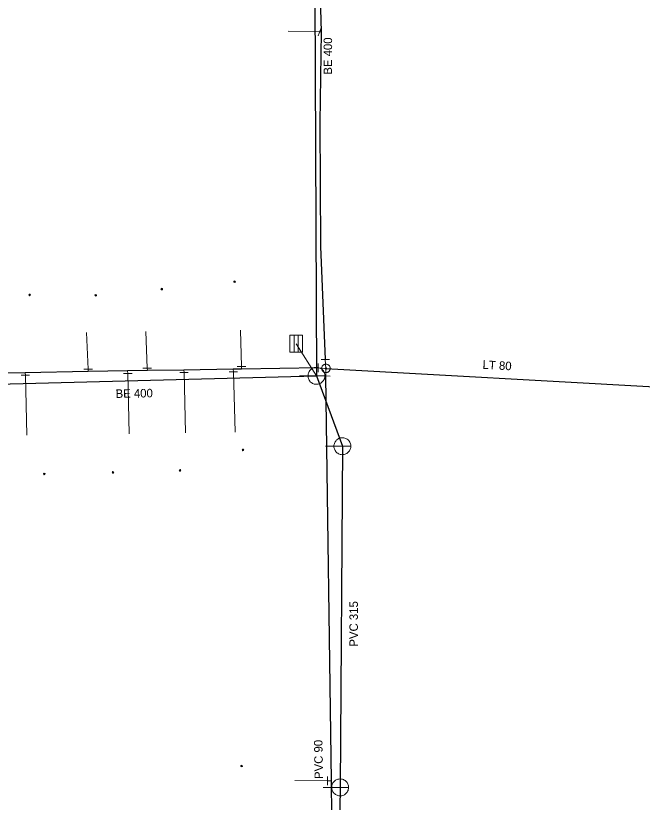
# Model space of a CAD drawing. Extents: x -783064 to -782702, y -1007904 to -1007145.
# Drawn here: x -782974.9 to -782901, y -1007605.1 to -1007512.4 of the extents above; entities that cross this region are included whole.
import ezdxf

# ---------------------------------------------------------------- set-up
doc = ezdxf.new("R2010")
doc.units = 0
doc.header["$LTSCALE"] = 0.4
doc.header["$PDMODE"] = 32
doc.header["$PDSIZE"] = 0.2
for name, color, linetype, lineweight in [('1', 7, 'Continuous', 13), ('11', 7, 'Continuous', 13), ('13', 7, 'Continuous', 13), ('14', 7, 'Continuous', 13), ('17', 7, 'Continuous', 25), ('22', 7, 'Continuous', 13), ('34', 7, 'Continuous', 13), ('47', 7, 'Continuous', 13)]:
    doc.layers.add(name, color=color, linetype=linetype, lineweight=lineweight)

msp = doc.modelspace()

# ---------------------------------------------------------------- linework, layer by layer
at = {"layer": '1'}
for p in [(-782949.079, -1007543.779), (-782973.239, -1007545.329), (-782965.44, -1007545.379), (-782957.66, -1007544.649), (-782948.094, -1007563.596), (-782971.51, -1007566.429), (-782963.42, -1007566.249), (-782955.51, -1007566.019), (-782948.26, -1007600.839)]:
    msp.add_point(p, dxfattribs=at)
at = {"layer": '11'}
msp.add_line((-782941.826, -1007551.093), (-782939.43, -1007554.87), dxfattribs=at)
at = {"layer": '13'}
for p, q in [((-782939.046, -1007514.346), (-782942.776, -1007514.276)), ((-782966.34, -1007554.077), (-782966.541, -1007549.761)), ((-782959.379, -1007553.96), (-782959.526, -1007549.655)), ((-782948.262, -1007553.772), (-782948.368, -1007549.481)), ((-782961.668, -1007554.598), (-782961.517, -1007561.686)), ((-782955.041, -1007554.486), (-782954.849, -1007561.594)), ((-782949.223, -1007554.388), (-782949.024, -1007561.522)), ((-782973.745, -1007554.801), (-782973.568, -1007561.852)), ((-782938.129, -1007602.576), (-782941.986, -1007602.551))]:
    msp.add_line(p, q, dxfattribs=at)
at = {"layer": '14', "lineweight": 25}
for p, q in [((-782939.739, -1007477.92), (-782939.43, -1007554.87)), ((-782980.87, -1007555.95), (-782939.43, -1007554.87)), ((-782939.43, -1007554.87), (-782936.37, -1007563.16)), ((-782936.37, -1007563.16), (-782936.64, -1007603.36))]:
    msp.add_line(p, q, dxfattribs=at)
at = {"layer": '14'}
for p, q in [((-782938.89, -1007514.33), (-782939.046, -1007514.346)), ((-782938.307, -1007553.995), (-782938.382, -1007552.936)), ((-782973.749, -1007554.501), (-782973.745, -1007554.801)), ((-782966.33, -1007554.376), (-782966.34, -1007554.077)), ((-782961.684, -1007554.298), (-782961.668, -1007554.598)), ((-782959.356, -1007554.259), (-782959.379, -1007553.96)), ((-782955.049, -1007554.187), (-782955.041, -1007554.486)), ((-782949.238, -1007554.089), (-782949.223, -1007554.388)), ((-782948.264, -1007554.072), (-782948.262, -1007553.772)), ((-782938.307, -1007553.995), (-782939.219, -1007553.92)), ((-782938.316, -1007554.89), (-782938.307, -1007553.995)), ((-782937.658, -1007602.569), (-782938.129, -1007602.576))]:
    msp.add_line(p, q, dxfattribs=at)
at = {"layer": '14', "lineweight": 25}
msp.add_lwpolyline([(-782936.64, -1007603.36), (-782936.751, -1007610.844), (-782936.908, -1007621.4), (-782936.693, -1007635.132), (-782936.562, -1007643.547), (-782936.402, -1007653.759), (-782936.365, -1007656.127)], dxfattribs=at)
at = {"layer": '17'}
msp.add_line((-782938.307, -1007553.995), (-782896.535, -1007556.337), dxfattribs=at)
for points in [[(-782931.92, -1007401.104), (-782931.956, -1007401.549), (-782932.488, -1007408.389), (-782933.956, -1007428.826), (-782935.107, -1007441.291), (-782936.401, -1007452.394), (-782937.129, -1007459.088), (-782938.934, -1007480.861), (-782939.259, -1007494.042), (-782939.179, -1007503.419), (-782938.89, -1007514.33), (-782939.048, -1007525.032), (-782938.934, -1007539.638), (-782938.382, -1007552.936)], [(-782939.219, -1007553.92), (-782948.264, -1007554.072), (-782949.238, -1007554.089), (-782955.049, -1007554.187), (-782959.356, -1007554.259), (-782961.684, -1007554.298), (-782966.33, -1007554.376), (-782973.749, -1007554.501), (-782976.004, -1007554.539), (-782980.237, -1007554.611), (-782981.137, -1007554.626), (-782987.183, -1007554.728), (-782991.244, -1007554.796), (-783006.674, -1007555.056), (-783010.241, -1007555.116), (-783023.002, -1007555.331)], [(-782936.879, -1007760.179), (-782936.971, -1007722.832), (-782936.999, -1007711.613), (-782937.04, -1007694.997), (-782937.068, -1007683.726), (-782937.09, -1007675.07), (-782937.095, -1007674.518), (-782937.094, -1007667.442), (-782937.091, -1007653.195), (-782937.09, -1007643.8), (-782937.227, -1007633.864), (-782937.409, -1007620.623), (-782937.602, -1007606.683), (-782937.658, -1007602.569), (-782938.316, -1007554.89)]]:
    msp.add_lwpolyline(points, dxfattribs=at)
at = {"layer": '22'}
for p, q in [((-782942.069, -1007550.081), (-782942.069, -1007552.081)), ((-782941.569, -1007550.082), (-782941.569, -1007552.082)), ((-782941.43, -1007554.869), (-782938.43, -1007554.87)), ((-782938.37, -1007563.159), (-782935.37, -1007563.16)), ((-782938.64, -1007603.359), (-782935.64, -1007603.36))]:
    msp.add_line(p, q, dxfattribs=at)
for points in [[(-782941.069, -1007550.082), (-782941.069, -1007552.082), (-782942.569, -1007552.081), (-782942.569, -1007550.081)], [(-782939.43, -1007555.869), (-782939.321, -1007555.864), (-782939.213, -1007555.846), (-782939.107, -1007555.816), (-782939.006, -1007555.776), (-782938.909, -1007555.724), (-782938.819, -1007555.662), (-782938.736, -1007555.59), (-782938.662, -1007555.51), (-782938.596, -1007555.422), (-782938.541, -1007555.328), (-782938.496, -1007555.228), (-782938.463, -1007555.123), (-782938.441, -1007555.016), (-782938.431, -1007554.907), (-782938.433, -1007554.797), (-782938.447, -1007554.689), (-782938.472, -1007554.582), (-782938.509, -1007554.479), (-782938.558, -1007554.381), (-782938.616, -1007554.289), (-782938.685, -1007554.203), (-782938.762, -1007554.126), (-782938.848, -1007554.057), (-782938.94, -1007553.998), (-782939.038, -1007553.95), (-782939.141, -1007553.913), (-782939.248, -1007553.887), (-782939.356, -1007553.873), (-782939.466, -1007553.87), (-782939.575, -1007553.88), (-782939.682, -1007553.901), (-782939.786, -1007553.935), (-782939.886, -1007553.979), (-782939.981, -1007554.034), (-782940.069, -1007554.1), (-782940.149, -1007554.174), (-782940.221, -1007554.257), (-782940.283, -1007554.347), (-782940.335, -1007554.443), (-782940.376, -1007554.545), (-782940.406, -1007554.65), (-782940.424, -1007554.758), (-782940.43, -1007554.868), (-782940.424, -1007554.977), (-782940.406, -1007555.085), (-782940.377, -1007555.19), (-782940.336, -1007555.292), (-782940.284, -1007555.389), (-782940.222, -1007555.479), (-782940.151, -1007555.562), (-782940.071, -1007555.637), (-782939.983, -1007555.702), (-782939.889, -1007555.758), (-782939.789, -1007555.802), (-782939.685, -1007555.836), (-782939.577, -1007555.858), (-782939.468, -1007555.868)], [(-782936.37, -1007564.159), (-782936.261, -1007564.154), (-782936.153, -1007564.136), (-782936.047, -1007564.106), (-782935.946, -1007564.066), (-782935.849, -1007564.014), (-782935.759, -1007563.952), (-782935.676, -1007563.88), (-782935.602, -1007563.8), (-782935.536, -1007563.712), (-782935.481, -1007563.618), (-782935.436, -1007563.518), (-782935.403, -1007563.413), (-782935.381, -1007563.306), (-782935.371, -1007563.197), (-782935.373, -1007563.087), (-782935.387, -1007562.979), (-782935.412, -1007562.872), (-782935.449, -1007562.769), (-782935.498, -1007562.671), (-782935.556, -1007562.579), (-782935.625, -1007562.493), (-782935.702, -1007562.416), (-782935.788, -1007562.347), (-782935.88, -1007562.288), (-782935.978, -1007562.24), (-782936.081, -1007562.203), (-782936.188, -1007562.177), (-782936.296, -1007562.163), (-782936.406, -1007562.16), (-782936.515, -1007562.17), (-782936.622, -1007562.191), (-782936.726, -1007562.225), (-782936.826, -1007562.269), (-782936.921, -1007562.324), (-782937.009, -1007562.39), (-782937.089, -1007562.464), (-782937.161, -1007562.547), (-782937.223, -1007562.637), (-782937.275, -1007562.733), (-782937.316, -1007562.835), (-782937.346, -1007562.94), (-782937.364, -1007563.048), (-782937.37, -1007563.158), (-782937.364, -1007563.267), (-782937.346, -1007563.375), (-782937.317, -1007563.48), (-782937.276, -1007563.582), (-782937.224, -1007563.679), (-782937.162, -1007563.769), (-782937.091, -1007563.852), (-782937.011, -1007563.927), (-782936.923, -1007563.992), (-782936.829, -1007564.048), (-782936.729, -1007564.092), (-782936.625, -1007564.126), (-782936.517, -1007564.148), (-782936.408, -1007564.158)], [(-782936.64, -1007604.359), (-782936.531, -1007604.354), (-782936.423, -1007604.336), (-782936.317, -1007604.306), (-782936.216, -1007604.266), (-782936.119, -1007604.214), (-782936.029, -1007604.152), (-782935.946, -1007604.08), (-782935.872, -1007604), (-782935.806, -1007603.912), (-782935.751, -1007603.818), (-782935.706, -1007603.718), (-782935.673, -1007603.613), (-782935.651, -1007603.506), (-782935.641, -1007603.397), (-782935.643, -1007603.287), (-782935.657, -1007603.179), (-782935.682, -1007603.072), (-782935.719, -1007602.969), (-782935.768, -1007602.871), (-782935.826, -1007602.779), (-782935.895, -1007602.693), (-782935.972, -1007602.616), (-782936.058, -1007602.547), (-782936.15, -1007602.488), (-782936.248, -1007602.44), (-782936.351, -1007602.403), (-782936.458, -1007602.377), (-782936.566, -1007602.363), (-782936.676, -1007602.36), (-782936.785, -1007602.37), (-782936.892, -1007602.391), (-782936.996, -1007602.425), (-782937.096, -1007602.469), (-782937.191, -1007602.524), (-782937.279, -1007602.59), (-782937.359, -1007602.664), (-782937.431, -1007602.747), (-782937.493, -1007602.837), (-782937.545, -1007602.933), (-782937.586, -1007603.035), (-782937.616, -1007603.14), (-782937.634, -1007603.248), (-782937.64, -1007603.358), (-782937.634, -1007603.467), (-782937.616, -1007603.575), (-782937.587, -1007603.68), (-782937.546, -1007603.782), (-782937.494, -1007603.879), (-782937.432, -1007603.969), (-782937.361, -1007604.052), (-782937.281, -1007604.127), (-782937.193, -1007604.192), (-782937.099, -1007604.248), (-782936.999, -1007604.292), (-782936.895, -1007604.326), (-782936.787, -1007604.348), (-782936.678, -1007604.358)]]:
    msp.add_lwpolyline(points, close=True, dxfattribs=at)
at = {"layer": '34'}
for p, q in [((-782938.885, -1007513.872), (-782939.207, -1007514.819)), ((-782939.222, -1007554.419), (-782939.214, -1007553.42)), ((-782938.881, -1007552.932), (-782937.882, -1007552.94)), ((-782965.84, -1007554.076), (-782966.84, -1007554.076)), ((-782961.168, -1007554.597), (-782962.168, -1007554.597)), ((-782958.879, -1007553.959), (-782959.879, -1007553.959)), ((-782954.541, -1007554.485), (-782955.541, -1007554.485)), ((-782948.723, -1007554.387), (-782949.723, -1007554.387)), ((-782947.762, -1007553.771), (-782948.762, -1007553.771)), ((-782973.245, -1007554.8), (-782974.245, -1007554.8)), ((-782938.815, -1007554.886), (-782937.816, -1007554.894)), ((-782938.136, -1007602.076), (-782938.122, -1007603.075))]:
    msp.add_line(p, q, dxfattribs=at)
at = {"layer": '47'}
for points in [[(-782938.262, -1007554.493), (-782938.21, -1007554.485), (-782938.159, -1007554.472), (-782938.111, -1007554.454), (-782938.064, -1007554.432), (-782938.019, -1007554.404), (-782937.978, -1007554.371), (-782937.941, -1007554.334), (-782937.907, -1007554.294), (-782937.878, -1007554.251), (-782937.853, -1007554.205), (-782937.833, -1007554.156), (-782937.82, -1007554.106), (-782937.81, -1007554.055), (-782937.807, -1007554.002), (-782937.808, -1007553.95), (-782937.816, -1007553.898), (-782937.829, -1007553.847), (-782937.847, -1007553.798), (-782937.869, -1007553.752), (-782937.897, -1007553.707), (-782937.93, -1007553.666), (-782937.967, -1007553.628), (-782938.007, -1007553.594), (-782938.05, -1007553.565), (-782938.096, -1007553.541), (-782938.145, -1007553.521), (-782938.195, -1007553.507), (-782938.246, -1007553.498), (-782938.299, -1007553.495), (-782938.351, -1007553.496), (-782938.403, -1007553.504), (-782938.454, -1007553.517), (-782938.503, -1007553.534), (-782938.549, -1007553.557), (-782938.594, -1007553.585), (-782938.635, -1007553.617), (-782938.673, -1007553.654), (-782938.707, -1007553.694), (-782938.736, -1007553.738), (-782938.76, -1007553.784), (-782938.78, -1007553.833), (-782938.794, -1007553.883), (-782938.803, -1007553.934), (-782938.806, -1007553.987), (-782938.805, -1007554.039), (-782938.797, -1007554.091), (-782938.784, -1007554.142), (-782938.767, -1007554.19), (-782938.744, -1007554.237), (-782938.716, -1007554.282), (-782938.684, -1007554.323), (-782938.647, -1007554.36), (-782938.607, -1007554.394), (-782938.563, -1007554.423), (-782938.517, -1007554.448), (-782938.468, -1007554.468), (-782938.419, -1007554.481), (-782938.367, -1007554.491), (-782938.314, -1007554.494)], [(-782938.299, -1007554.076), (-782938.29, -1007554.075), (-782938.282, -1007554.073), (-782938.275, -1007554.07), (-782938.267, -1007554.066), (-782938.259, -1007554.062), (-782938.253, -1007554.056), (-782938.246, -1007554.05), (-782938.241, -1007554.044), (-782938.236, -1007554.036), (-782938.232, -1007554.029), (-782938.229, -1007554.021), (-782938.227, -1007554.012), (-782938.225, -1007554.004), (-782938.224, -1007553.996), (-782938.225, -1007553.987), (-782938.226, -1007553.978), (-782938.228, -1007553.97), (-782938.231, -1007553.963), (-782938.235, -1007553.955), (-782938.239, -1007553.947), (-782938.245, -1007553.941), (-782938.251, -1007553.934), (-782938.257, -1007553.929), (-782938.265, -1007553.923), (-782938.272, -1007553.92), (-782938.28, -1007553.917), (-782938.289, -1007553.915), (-782938.297, -1007553.913), (-782938.305, -1007553.912), (-782938.314, -1007553.913), (-782938.323, -1007553.914), (-782938.331, -1007553.916), (-782938.338, -1007553.919), (-782938.346, -1007553.923), (-782938.354, -1007553.927), (-782938.36, -1007553.932), (-782938.367, -1007553.939), (-782938.372, -1007553.945), (-782938.378, -1007553.953), (-782938.381, -1007553.96), (-782938.384, -1007553.968), (-782938.386, -1007553.977), (-782938.388, -1007553.985), (-782938.389, -1007553.993), (-782938.388, -1007554.002), (-782938.387, -1007554.011), (-782938.385, -1007554.019), (-782938.382, -1007554.026), (-782938.378, -1007554.034), (-782938.374, -1007554.042), (-782938.369, -1007554.048), (-782938.362, -1007554.055), (-782938.356, -1007554.06), (-782938.348, -1007554.065), (-782938.341, -1007554.069), (-782938.333, -1007554.072), (-782938.324, -1007554.074), (-782938.316, -1007554.076), (-782938.308, -1007554.077)]]:
    msp.add_lwpolyline(points, close=True, dxfattribs=at)

# ---------------------------------------------------------------- texts
at = {"layer": '1'}
for s, rotation, p in [('BE 400', 90, (-782937.586, -1007519.385)), ('LT 80 ', 357, (-782919.862, -1007554.042)), ('BE 400', 1, (-782963.096, -1007557.471)), ('PVC 315 ', 90, (-782934.542, -1007586.772)), ('PVC 90', 91, (-782938.646, -1007602.357))]:
    msp.add_text(s, height=1, rotation=rotation, dxfattribs=at).set_placement(p)

doc.saveas('drawing.dxf')
